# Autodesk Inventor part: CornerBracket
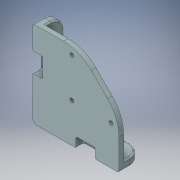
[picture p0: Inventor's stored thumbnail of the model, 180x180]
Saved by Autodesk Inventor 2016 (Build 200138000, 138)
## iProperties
Created: 2016-01
Part Number: CornerBracket
Material: Generic
Document SubType Name: Modeling
Designer: John
Density: 1 g/cm^3
Appearance: Default
Author: John
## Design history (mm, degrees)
feature "SOLID1"
node "Direct Edit1"
sketch "Sketch1"
  geometry: L1 (-1.5, 4)-(21.4, 4) reference; L2 (-4, -21.4)-(-4, 1.5) reference; L3 (0, -26.4)-(-9, -26.4) reference; L4 (0, 0)-(0, -26.4) reference; L5 (26.4, 0)-(0, 0) reference; L6 (26.4, 9)-(26.4, 0) reference; L7 (0.3, -0.3)-(26.1, -0.3); L8 (26.1, -0.3)-(26.1, -26.1); L9 (26.1, -26.1)-(0.3, -26.1); L10 (0.3, -26.1)-(0.3, -0.3); L11 (0, 0)-(26.4, 0); L12 (26.4, 0)-(26.4, -26.4); L13 (26.4, -26.4)-(0, -26.4); L14 (0, -26.4)-(0, 0); A1 r 2.5 centre (-1.5, 1.5) between (-1.5, 4) and (-4, 1.5) reference; A2 r 5 centre (-9, -21.4) between (-9, -26.4) and (-4, -21.4) reference; A3 r 5 centre (21.4, 9) between (21.4, 4) and (26.4, 9) reference; 1 further point
  constraints: 16 end point, 4 parallel, 3 perpendicular, 2 horizontal
  dimensions: "d6" = 0.3 distance between parallel lines of L5 L7; "d7" = 0.3 distance between parallel lines of L4 L10 (= d6); "d8" = 25.8 distance of L7.start L7.end
extrude "Extrusion1" join sketch "Sketch1" stored distance "d9" = 10; taper "d10" = 0 deg
sketch "Sketch2"
  geometry: L1 (-135.815, 166.787)-(168.899, 166.787); L2 (168.899, 166.787)-(168.899, -103.29); L3 (168.899, -103.29)-(-135.815, -103.29); L4 (-135.815, -103.29)-(-135.815, 166.787); 1 further point
  constraints: 8 end point, 2 parallel, 1 horizontal, 1 perpendicular
extrude "Extrusion2" cut sketch "Sketch2" stored distance "d11" = 0; taper "d12" = 0 deg
sketch "Sketch3"
  geometry: L1 (0, 0)-(22.9, 0) reference; L2 (22.9, 0)-(22.9, 25) reference; L3 (22.9, 25)-(0, 25) reference; L4 (0, 25)-(0, 0) reference; C1 r 3 at (7.7, 11.6) reference; C2 r 3.25 at (7.7, 11.6); 1 further point
  constraints: 1 centre point
  dimensions: "d13" = 6.5 diameter of C2
extrude "Extrusion3" cut sketch "Sketch3" stored distance "d14" = 10; taper "d15" = 0 deg
sketch "Sketch4"
  geometry: L1 (25, 0)-(25, 22.9) reference; L2 (25, 22.9)-(0, 22.9) reference; L3 (0, 22.9)-(0, 0) reference; L4 (0, 0)-(25, 0) reference; C1 r 3 at (11.6, 7.7) reference; C2 r 3.25 at (11.6, 7.7); 1 further point
  constraints: 1 centre point
  dimensions: "d16" = 6.5 diameter of C2
extrude "Extrusion4" cut sketch "Sketch4" stored distance "d17" = 10; taper "d18" = 0 deg
fillet "Fillet1" dims "d19" = 2
body "Solid1"
node "Projected Loop1"
node "Projected Loop2"
node "Projected Loop3"
move_body "Move1" dims "d2" = -20
move_body "Move2" dims "d4" = 8
other parameters: "d0" = 0, "d1" = 0, "d3" = 0, "d5" = 0
